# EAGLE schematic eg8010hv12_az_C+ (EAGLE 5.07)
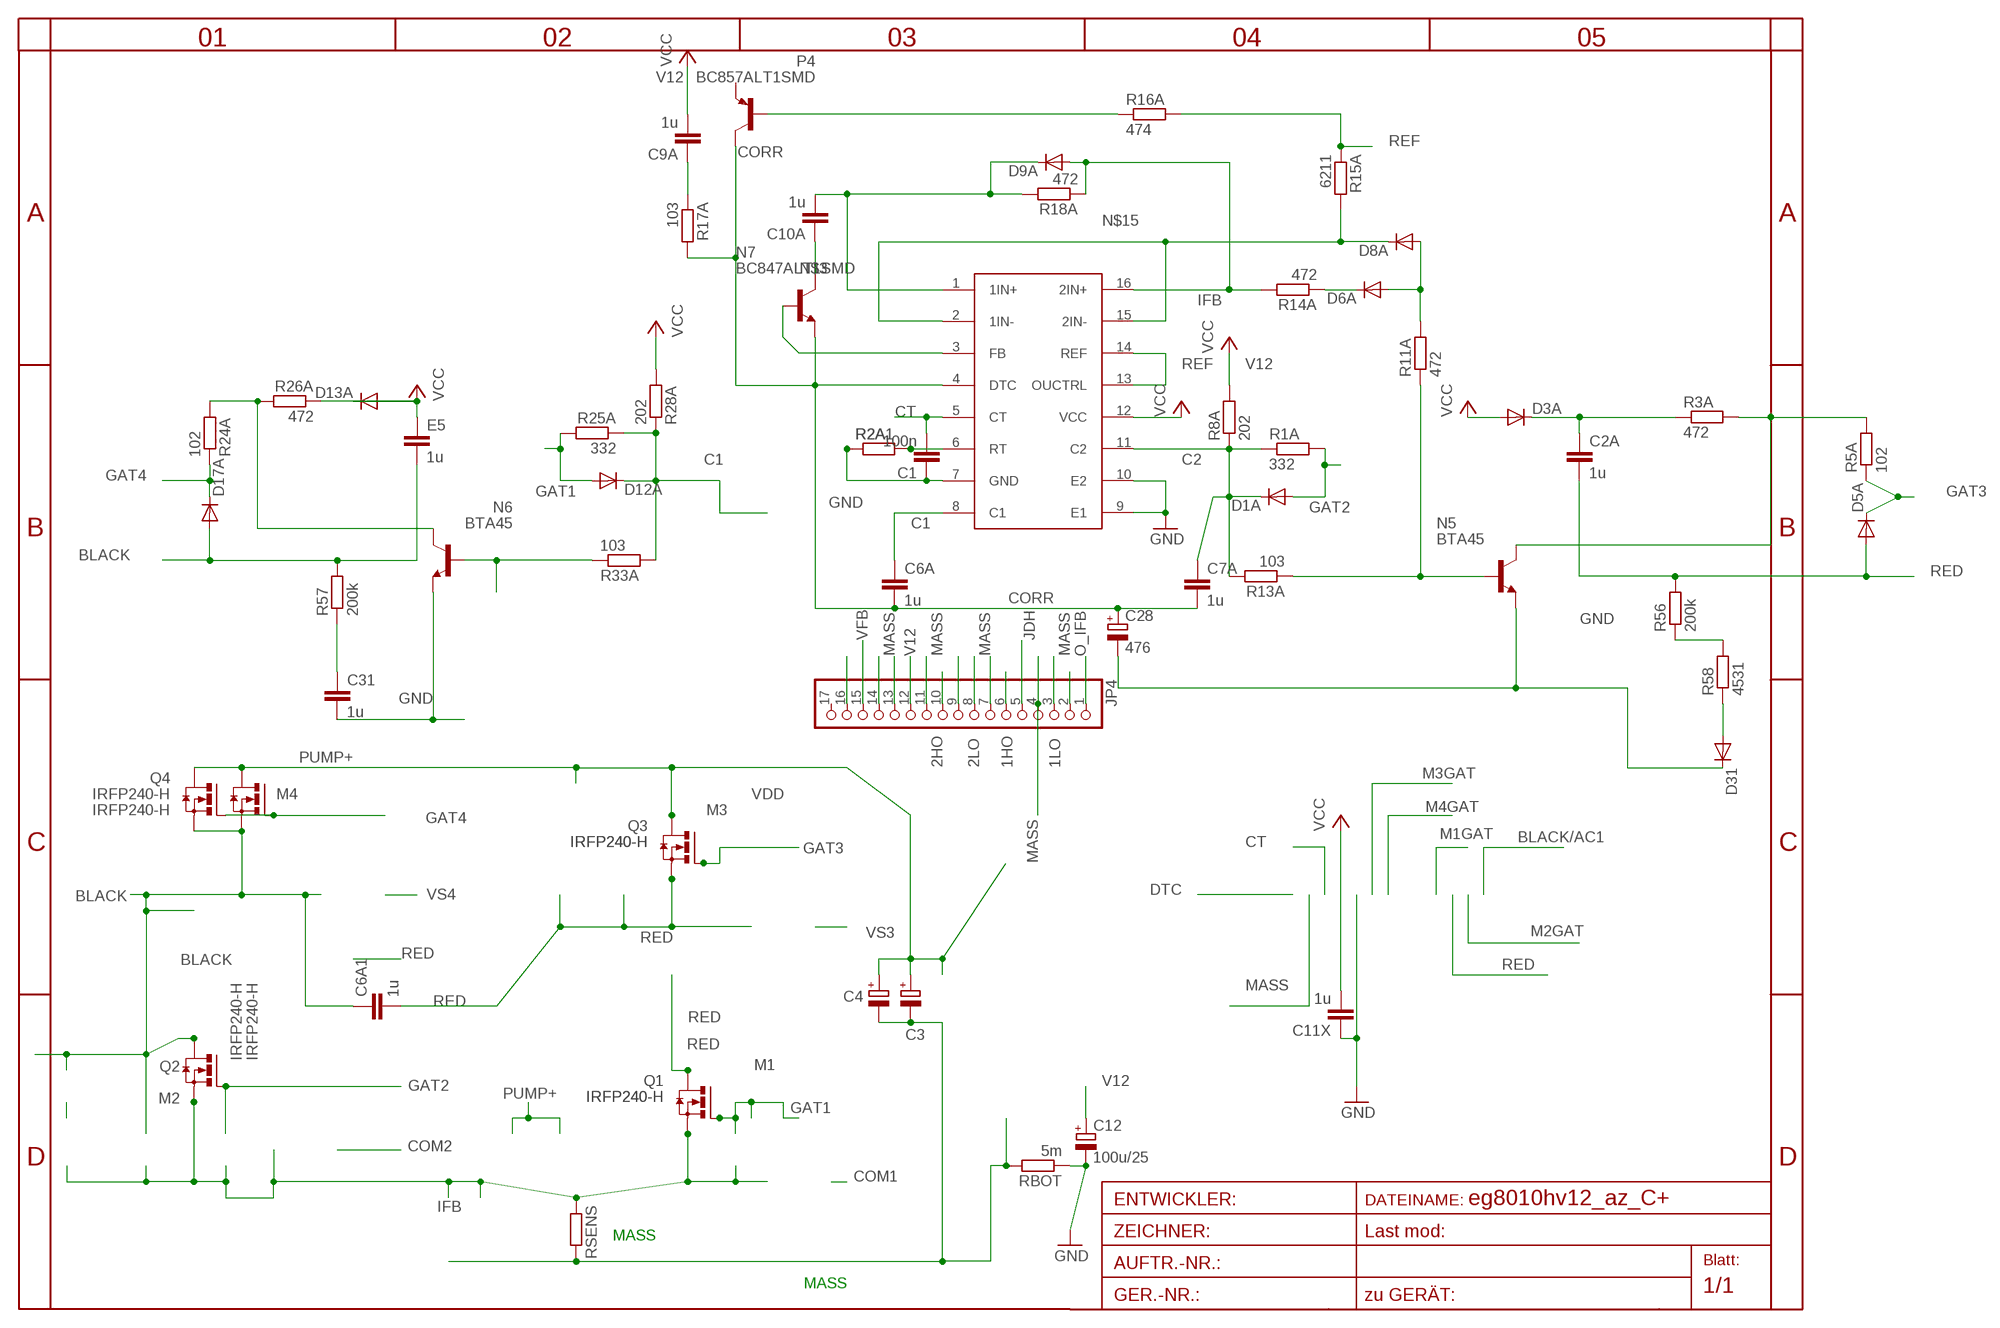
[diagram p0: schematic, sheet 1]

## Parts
C1  100n  C-EUC0805  [C0805]
C2A  1u  C-EUC1206  [C1206]
C3  CPOL-EUE5-13  [E5-13]
C4  CPOL-EUE5-13  [E5-13]
C6A  1u  C-EUC0805  [C0805]
C6A1  1u  C-EU050-024X044  [C050-024X044]
C7A  1u  C-EUC0805  [C0805]
C9A  1u  C-EUC0805  [C0805]
C10A  1u  C-EUC1206  [C1206]
C11X  1u  C-EUC1206  [C1206]
C12  100u/25  CPOL-EUD  [PANASONIC_D]
C28  476  CPOL-EUD  [PANASONIC_D]
C31  1u  C-EUC1206  [C1206]
D1A  DIODE-MINIMELF  [MINIMELF]
D3A  DIODE-SMA-DO214  [SMA-DO214AC]
D5A  DIODE-MINIMELF  [MINIMELF]
D6A  DIODE-MINIMELF  [MINIMELF]
D8A  DIODE-MINIMELF  [MINIMELF]
D9A  DIODE-MINIMELF  [MINIMELF]
D12A  DIODE-MINIMELF  [MINIMELF]
D13A  DIODE-SMA-DO214  [SMA-DO214AC]
D17A  DIODE-MINIMELF  [MINIMELF]
D31  DIODE-MINIMELF  [MINIMELF]
E5  1u  C-EUC1206  [C1206]
JP4  PINHD-1X17  [1X17]
M1  IRFP240-H  [TO247BH]
M2  IRFP240-H  [TO247BH]
M3  IRFP240-H  [TO247BH]
M4  IRFP240-H  [TO247BH]
N5  BTA45  SMBTA45HV  [SOT23HV]
N6  BTA45  SMBTA45HV  [SOT23HV]
N7  BC847ALT1SMD  [SOT23]
P4  BC857ALT1SMD  [SOT23-BEC]
Q1  IRFP240-H  [TO247BH]
Q2  IRFP240-H  [TO247BH]
Q3  IRFP240-H  [TO247BH]
Q4  IRFP240-H  [TO247BH]
R1A  332  R-EU_R0805  [R0805]
R2A  R-EU_R0805  [R0805]
R2A1  R-EU_R0805  [R0805]
R3A  472  R-EU_R0805  [R0805]
R5A  102  R-EU_R1206  [R1206]
R8A  202  R-EU_R0805  [R0805]
R11A  472  R-EU_R0805  [R0805]
R13A  103  R-EU_R0805  [R0805]
R14A  472  R-EU_R0805  [R0805]
R15A  6211  R-EU_R1206  [R1206]
R16A  474  R-EU_R1206  [R1206]
R17A  103  R-EU_R1206  [R1206]
R18A  472  R-EU_R0805  [R0805]
R24A  102  R-EU_R1206  [R1206]
R25A  332  R-EU_R0805  [R0805]
R26A  472  R-EU_R0805  [R0805]
R28A  202  R-EU_R0805  [R0805]
R33A  103  R-EU_R0805  [R0805]
R56  200k  R-EU_R0805  [R0805]
R57  200k  R-EU_R0805  [R0805]
R58  4531  R-EU_R0805  [R0805]
RBOT  5m  R-EU_0204/7  [0204/7]
RSENS  R-EU_WIRE  [WIRE]
U$5  AZ7500SO16  [SO16]

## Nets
1HO: JP4.6
1LO: JP4.3
2HO: JP4.10
2LO: JP4.8
BLACK: C6A1.1 D17A.A E5.2 M2.D M4.S Q2.D Q4.S R57.2
C1: C6A.1 D12A.C R25A.1 R28A.1 R33A.2 U$5.8(C1)
C2: C7A.1 D1A.C R1A.1 R8A.1 R13A.2 U$5.11(C2)
CORR: C6A.2 C7A.2 C28.+ N7.2(E) P4.C R17A.2 U$5.4(DTC)
CT: C1.2 U$5.5(CT)
DFG1: JP4.9
GAT1: D12A.A M1.G Q1.G R25A.2
GAT2: D1A.A M2.G Q2.G R1A.2
GAT3: D5A.C M3.G Q3.G R5A.1
GAT4: D17A.C M4.G Q4.G R24A.1
GND: C1.1 C11X.1 C12.- C28.- C31.2 D31.C N5.2(E) N6.2(E) R2A1.1 R2A.1 RBOT.1 U$5.7(GND) U$5.9(E1) U$5.10(E2)
IFB: D9A.A M1.S M2.S Q1.S Q2.S R14A.2 R18A.1 RSENS.1 U$5.16(2IN+)
JDH: JP4.5
MASS: C3.- C4.- JP4.2 JP4.4 JP4.7 JP4.11 JP4.13 RBOT.2 RSENS.2
N$3: C10A.2 D9A.C R18A.2 U$5.1(1IN+)
N$4: C2A.1 D3A.K(C) R3A.1
N$5: N5.3(C) R3A.2 R5A.2
N$11: N5.1(B) R11A.1 R13A.1
N$13: D6A.A D8A.A R11A.2
N$15: D8A.C R15A.2 U$5.2(1IN-) U$5.15(2IN-)
N$36: D6A.C R14A.1
N$37: P4.B R16A.1
N$38: R2A1.2 R2A.2 U$5.6(RT)
N$39: C9A.1 R17A.1
N$40: N7.1(B) U$5.3(FB)
N$41: C10A.1 N7.3(C)
N$42: D13A.K(C) E5.1 R26A.1
N$43: N6.3(C) R24A.2 R26A.2
N$44: N6.1(B) R33A.1
N$45: C31.1 R57.1
N$46: R56.1 R58.2
N$47: D31.A R58.1
O_IFB: JP4.1
PUMP+: C3.+ C4.+ M3.D M4.D Q3.D Q4.D
RED: C2A.2 C6A1.2 D5A.A M1.D M3.S Q1.D Q3.S R56.2
REF: R15A.1 R16A.2 U$5.13(OUCTRL) U$5.14(REF)
TFB: JP4.16
V12: C9A.2 C11X.2 C12.+ D3A.A D13A.A JP4.12 R8A.2 R28A.2 U$5.12(VCC) ; supply symbol labelled VCC
VDD: JP4.14
VFB: JP4.15
Unconnected: JP4.17 P4.E

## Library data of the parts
C1 C2A C6A C6A1 C7A C9A C10A C11X C31 E5 = rcl:C-EU: CAPACITOR, European symbol
C3 C4 C12 C28 = rcl:CPOL-EU: POLARIZED CAPACITOR, European symbol
D1A D3A D5A D6A D8A D9A D12A D13A D17A D31 = diode:DIODE-: DIODE
JP4 = pinhead:PINHD-1X17: PIN HEADER
M1-M4 Q1-Q4 = transistor-power:IRFP240: HEXFET Power MosFet Source: http://www.irf.com/
N5 N6 = transistor-npn:SMBTA45
N7 = transistor-npn:BC847*: NPN Transistor
P4 = transistor-pnp:BC857*: PNP Transistror
R1A R2A R2A1 R3A R5A R8A R11A R13A R14A R15A R16A R17A R18A R24A R25A R26A R28A R33A R56-R58 RBOT RSENS = rcl:R-EU_: RESISTOR, European symbol
U$5 = az7500:AZ7500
